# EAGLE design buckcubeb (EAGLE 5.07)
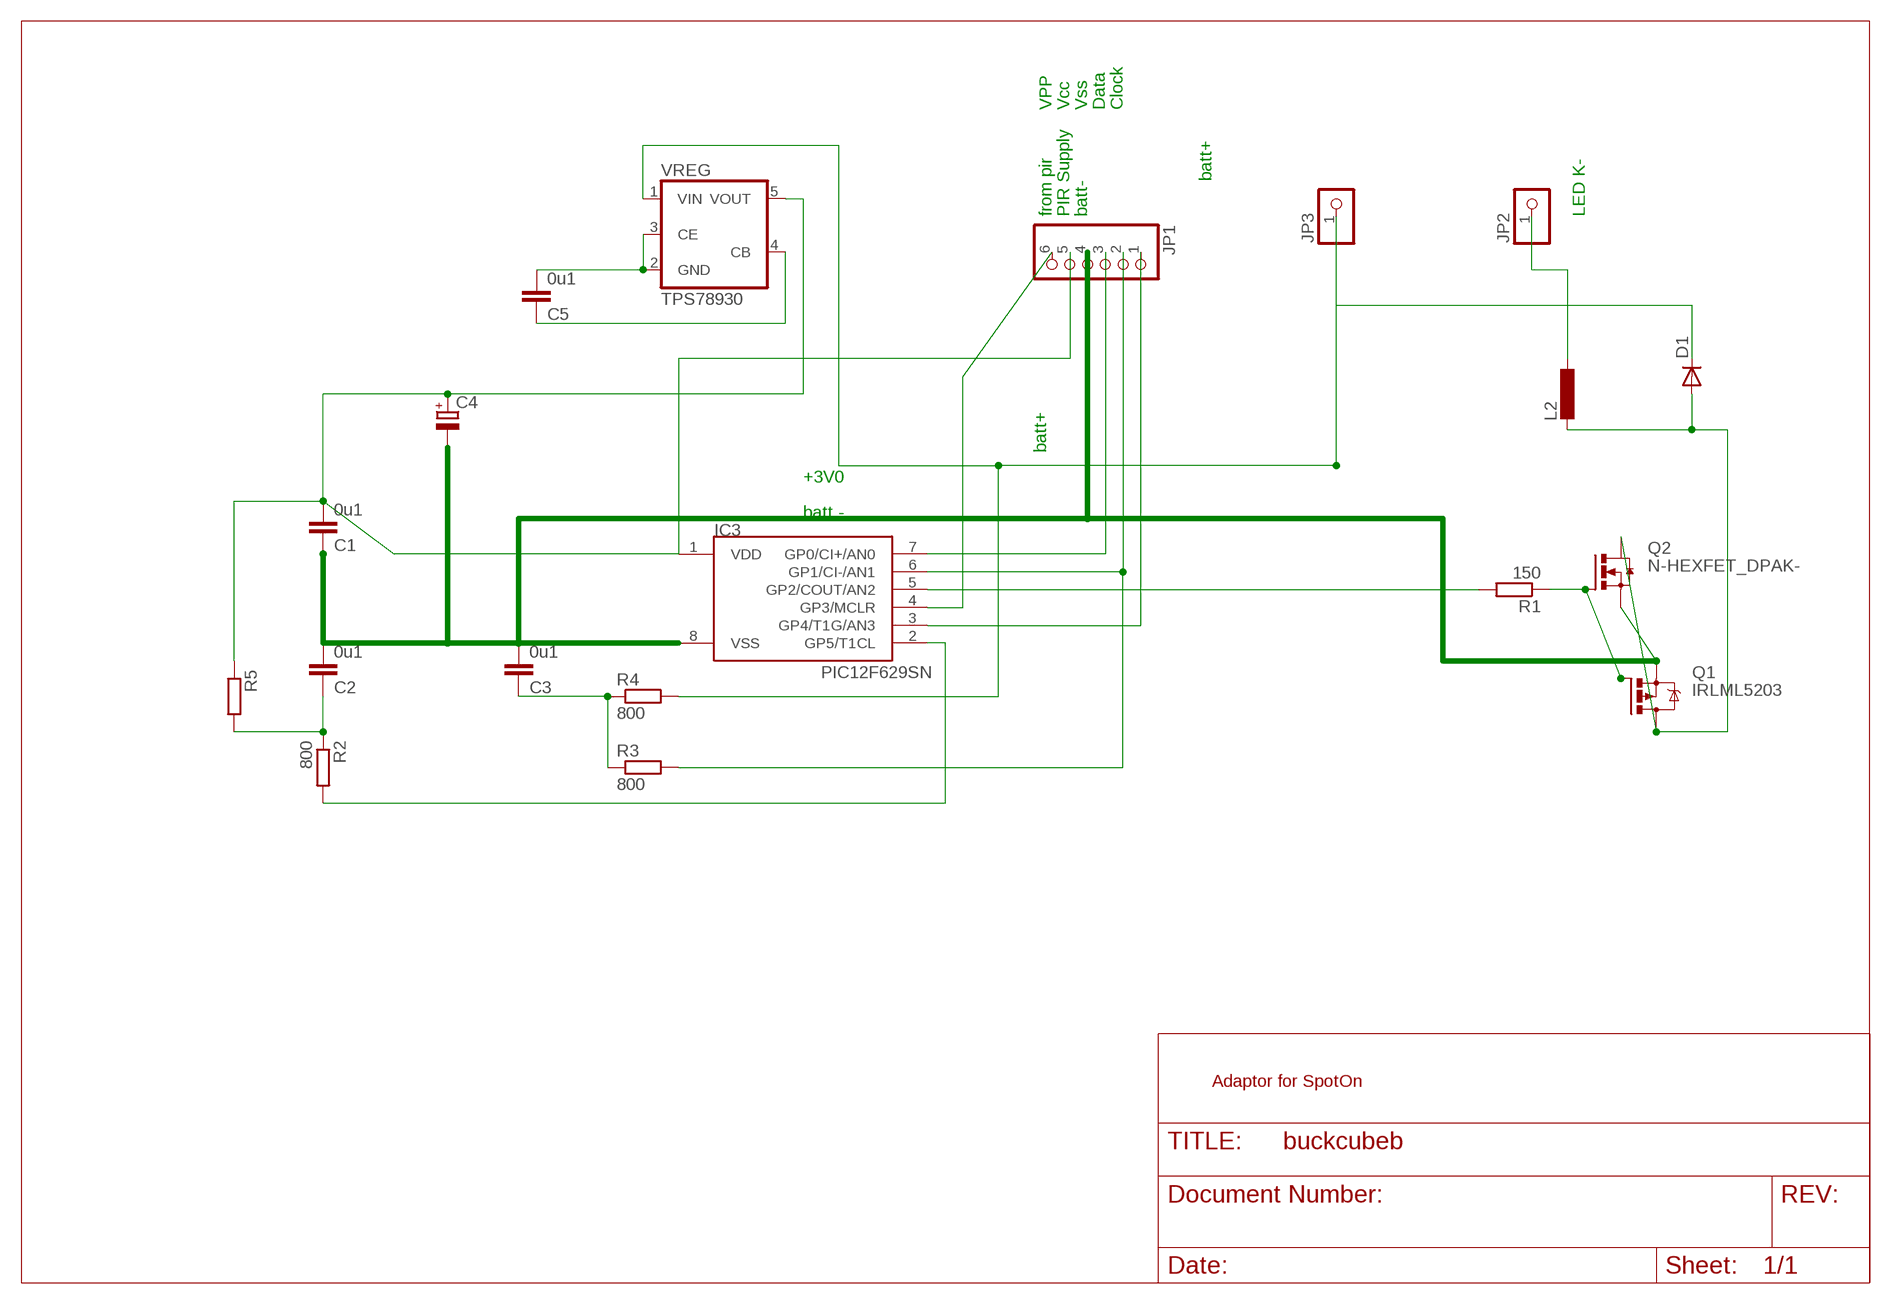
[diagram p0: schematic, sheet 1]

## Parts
C1  0u1  C-EUC1206  [C1206]
C2  0u1  C-EUC1206  [C1206]
C3  0u1  C-EUC1206  [C1206]
C4  CPOL-EUE2.5-6  [E2,5-6]
C5  0u1  C-EUC1206  [C1206]
D1  DIODE-SMC  [SMC]
IC3  PIC12F629SN  [SO-08]
JP1  PINHD-1X6  [1X06BOX]
JP2  PINHD-1X11X0.4  [1X01]
JP3  PINHD-1X11X0.4  [1X01]
L2  L-EUOPEN  [OPEN5]
Q1  IRLML5203  [MICRO3]
Q2  N-HEXFET_DPAK-  [TO252]
R1  150  R-EU_R1206  [R1206]
R2  800  R-EU_R1206  [R1206]
R3  800  R-EU_R1206  [R1206]
R4  800  R-EU_R1206  [R1206]
R5  R-EU_0411/3V  [0411V]
VREG  TPS78930  TPS78930SOT23-5  [SOT25]

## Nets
HOT: D1.A L2.2 Q1.3(D) Q2.3(D)
N$2: IC3.2(GP5/T1CL) R2.2
N$3: D1.C JP3.1 R4.2 VREG.1(VIN)
N$4: IC3.6(GP1/CI-/AN1) JP1.2 R3.2
N$6: JP2.1 L2.1
N$7: C3.1 R3.1 R4.1
N$11: C2.1 R2.1 R5.2
N$12: Q1.1(G) Q2.1(G) R1.1
N$13: C5.1 VREG.4(CB)
N$14: IC3.7(GP0/CI+/AN0) JP1.3
N$15: C5.2 VREG.2(GND) VREG.3(CE)
N$16: IC3.5(GP2/COUT/AN2) R1.2
N$17: IC3.3(GP4/T1G/AN3) JP1.1
V3: C1.2 C4.+ IC3.1(VDD) JP1.5 R5.1 VREG.5(VOUT)
VPP: IC3.4(GP3/MCLR) JP1.6
VSS: C1.1 C2.2 C3.2 C4.- IC3.8(VSS) JP1.4 Q1.2(S) Q2.2(S)

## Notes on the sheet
- VPP | Vcc | Vss | Data | Clock
- batt+
- from pir | PIR Supply | batt- | LED K-
- batt+
- +3V0
- batt -
- Adaptor for SpotOn

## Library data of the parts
C1-C3 C5 = rcl:C-EU: CAPACITOR, European symbol
C4 = rcl(2):CPOL-EU: POLARIZED CAPACITOR, European symbol
D1 = diode:DIODE-: DIODE
IC3 = microchip-3:PIC12F6*: uPC nW 1k Program Flash memory 2x Timer Comparator 10b A/D converter/ 4xIN
JP1 = pinhead:PINHD-1X6: PIN HEADER
JP2 JP3 = pinhead:PINHD-1X1: PIN HEADER
L2 = rcl:L-EU: INDUCTOR, European symbol
Q1 = transistor-power:IRLML5203: HEXFET P-Channel Power MOSFET
Q2 = transistor-power:N-HEXFET_?-*: HEXFET® Power MOSFET
R1-R5 = rcl:R-EU_: RESISTOR, European symbol
VREG = v-reg:TPS78930

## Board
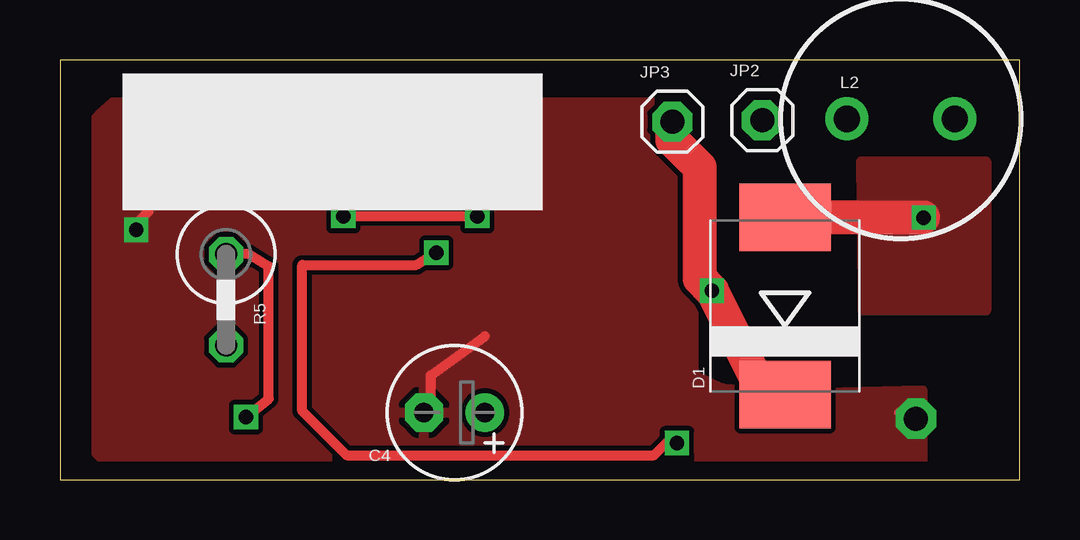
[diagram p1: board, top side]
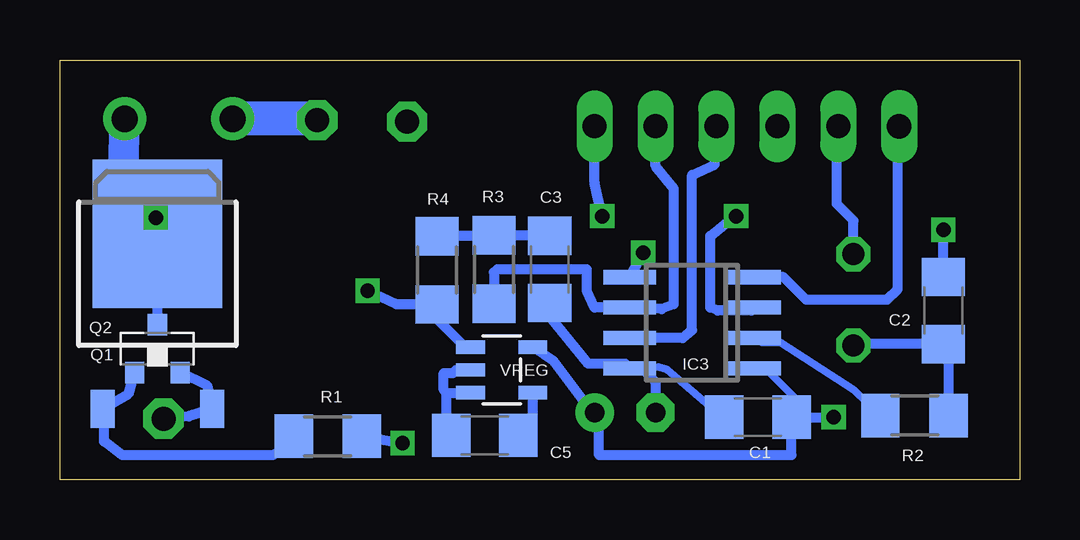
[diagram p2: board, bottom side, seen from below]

Size 40 x 17.5 mm. Coordinates in mm from the lower left corner, seen from the top.
Outline: 0,0 40,0 40,17.5 0,17.5 0,0
Copper layers (1*16): Top 0.035mm / dielectric 1.5mm / Bottom 0.035mm
Design rules "default *": minimum track width 10mil, minimum drill 14mil, track to track 8mil, track to pad 8mil, pad to pad 8mil, via to via 8mil, smd to smd 8mil, copper to edge 30mil, drill to drill 8mil, minimum pad ring 10mil, minimum via ring 8mil, stop-mask expansion 4mil, vias tented up to drill 0mil, thermal gap 10mil

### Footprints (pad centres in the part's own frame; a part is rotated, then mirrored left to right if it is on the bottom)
C1206 = smd 1.6 x 1.8: 1 -1.4,0; 2 1.4,0
E2,5-6 = drill 0.813 pad 1.6 round: + -1.27,0 | drill 0.813 pad 1.6 octagon: - 1.27,0
SMC = smd 2.8 x 3.8: A 3.7,0; C -3.7,0
SO-08 = smd 0.6 x 2.2: 1 -1.905,-2.6; 2 -0.635,-2.6; 3 0.635,-2.6; 4 1.905,-2.6; 5 1.905,2.6; 6 0.635,2.6; 7 -0.635,2.6; 8 -1.905,2.6
1X06BOX = drill 1 long: 1 -6.35,0; 2 -3.81,0; 3 -1.27,0; 4 1.27,0; 5 3.81,0 | drill 1.016 long: 6 6.35,0
1X01 = drill 1 pad 1.676 octagon: 1 0,0
OPEN5 = drill 1.1 pad 1.778 round: 1 -2.25,0; 2 2.25,0
MICRO3 = smd 0.8 x 0.9: 1 -0.95,-1; 2 0.95,-1; 3 0,1
TO252 = smd 1 x 1.6: 1 -2.28,-3.53; 2 2.28,-3.53 | smd 5.4 x 6.2: 3 0,3.77
R1206 = smd 1.6 x 1.803: 1 -1.422,0; 2 1.422,0
0411V = drill 0.914 octagon: 1 -2.54,0; 2 1.27,0
SOT25 = smd 0.55 x 1.2: 1 -0.95,-1.3; 2 0,-1.3; 3 0.95,-1.3; 4 0.95,1.3; 5 -0.95,1.3

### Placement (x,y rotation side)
C1  10.91,2.6 0 bottom
C2  3.17,7.05 90 bottom
C3  19.58,8.76 270 bottom
C4  16.45,2.79 180 top
C5  22.29,1.84 180 bottom
D1  30.23,7.24 90 top
IC3  13.65,6.54 90 bottom
JP1  11.37,14.73 180 top
JP2  29.27,14.99 0 top
JP3  25.53,14.92 0 top
L2  35.05,15.05 0 top
Q1  35.94,5.46 0 bottom
Q2  35.94,6.48 0 bottom
R1  28.83,1.81 0 bottom
R2  4.38,2.67 180 bottom
R3  21.91,8.76 270 bottom
R4  24.28,8.73 270 bottom
R5  6.92,6.86 270 top
VREG  21.59,4.57 270 bottom

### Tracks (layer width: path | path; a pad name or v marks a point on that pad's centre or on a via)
HOT  (via drill 0.6)
  Top 0.406: 35.99,10.94 v36.01,10.92
  Top 1.422: D1.A 35.99,10.94
  Bottom 0.406: v36.01,10.92 36.89,11.87 37.02,12.19 37.37,12.89 | Q2.3 Q1.3 35.94,6.4
  Bottom 1.27: 37.37,12.89 L2.2
  Bottom 1.422: v36.01,10.92 36.01,10.31 Q2.3
  pour Top: 33.4,13.27 38.61,13.27 38.61,7.05 33.46,7.05 33.46,7.87
N$2
  Bottom 0.305: R2.2 6.9,3.73 9.97,5.71 10.73,5.71 10.99,5.97 IC3.2
N$3  (via drill 0.6)
  Top 0.406: 29.21,3.81 D1.C
  Top 1.422: JP3.1 25.53,14.16 26.67,13.02 26.67,8.38 v27.18,7.87 29.21,3.81
  Bottom 0.406: VREG.1 23.11,5.52 24.28,6.69 R4.2 25.97,7.3 v27.18,7.87
N$4
  Bottom 0.406: R3.2 21.91,8.64 21.78,8.76 18.03,8.76 18.03,7.87 17.72,7.18 IC3.6 14.92,7.11 14.41,7.3 14.41,12.13 15.18,13.08 JP1.2
N$6
  Bottom 0.406: JP2.1 29.34,15.05
  Bottom 1.422: 29.34,15.05 L2.1
N$7
  Bottom 0.406: R4.1 21.95,10.15 R3.1 19.61,10.19 C3.1
N$11
  Bottom 0.406: R2.1 2.96,5.43 C2.1 6.86,5.65 R5.2
N$12
  Bottom 0.406: Q1.1 37.15,3.58 Q2.1 38.16,2.18 38.16,1.59 37.4,1.02 31.11,1.02 30.45,1.49 R1.1
N$13
  Bottom 0.406: VREG.4 20.29,2.44 C5.1
N$14
  Bottom 0.406: IC3.7 14.03,5.91 13.65,6.22 13.65,12.7 12.7,13.14 12.7,15.18 JP1.3
N$15
  Bottom 0.406: 23.88,3.62 VREG.3 | 23.88,3.62 24,3.75 24,4.45 23.62,4.45 23.5,4.57 VREG.2 | 23.88,3.62 23.88,2.03 C5.2
N$16  (via drill 0.6)
  Top 0.406: v25.72,1.52 25.27,1.52 24.77,1.02 11.94,1.02 10.1,2.86 10.1,8.95 14.86,8.95 v15.68,9.46
  Bottom 0.406: R1.2 25.72,1.49 v25.72,1.52 | v15.68,9.46 IC3.5
N$17  (via drill 0.6)
  Top 0.406: v11.81,10.99 v17.4,10.99
  Bottom 0.406: JP1.1 17.72,12.38 v17.4,10.99 | v11.81,10.99 11.81,11.05 12.89,10.16 12.89,7.18 12.57,7.05 11.18,7.05 IC3.3
V3  (via drill 0.6)
  Top 0.406: R5.1 7.87,9.4 8.7,8.89 8.7,3.37 v7.75,2.6
  Bottom 0.305: 11.3,4.64 IC3.1 10.48,4.51 9,3.03 C1.2
  Bottom 0.406: VREG.5 19.43,4.95 17.65,2.6 C4.+ 17.53,2.54 17.53,1.02 9.51,1.02 C1.2 v7.75,2.6 | R5.1 6.92,10.79 7.62,11.49 7.62,15.18 JP1.5
VPP
  Bottom 0.406: IC3.4 9.84,8.45 8.89,7.49 5.52,7.49 5.08,7.94 5.08,15.18 JP1.6
VSS  (via drill 0.6, 1 pad 1.68)
  Top 0.406: 17.71,5.97 15.46,4.35 15.46,2.82 C4.- | v3.17,10.41 3.17,10.67 3.68,11.18 | v35.69,2.54 34.99,2.79
  Bottom 0.305: IC3.8 15.77,4.66 15.05,4.7 14.7,4.6 12.33,2.55 C1.1
  Bottom 0.406: C4.- 15.18,4.07 15.77,4.66 | C3.2 19.58,6.82 17.97,4.83 16.44,4.83 IC3.8 | Q1.2 33.85,3.9 Q2.2 34.63,2.63 v35.69,2.54 | C2.2 v3.17,10.41
  pour Top: 2.22,15.75 25.34,15.75 26.42,14.67 26.42,4.38 27.62,3.81 30.99,3.62 35.94,3.75 35.94,0.57 31.05,0.38 2.22,0.38 1.52,1.08 1.52,15.11 1.59,15.18 1.65,15.18 1.65,15.24

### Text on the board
tValues: minus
